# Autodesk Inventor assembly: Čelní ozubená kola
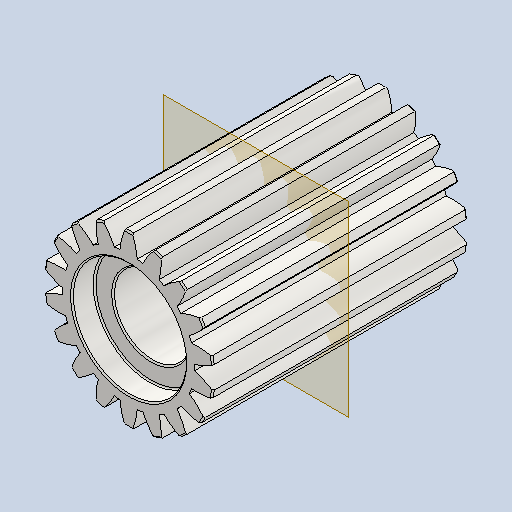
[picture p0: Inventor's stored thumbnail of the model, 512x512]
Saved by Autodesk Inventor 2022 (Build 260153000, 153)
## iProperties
ClientObjectVersion: 1
Created: 2025-05
Part Number: Čelní ozubená kola
Document SubType Name: Assembly
Designer: jbart
Categories: <?xml version="1.0" encoding="UTF-16"?> <MemberInstance><Categories><FamilyTemplate/><ParamToTemplateMap><ParamToTemplate><ParamToTemplate CategoryParameter="//
Mass: 8914.05 g
Surface Area: 1687.53 cm^2
Volume: 1135.55 cm^3
Density: 7.85 g/cm^3
Author: jbart
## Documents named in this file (2)
- C:\Users\jbart\OneDrive\Dokumenty\Inventor\Převodovka navijáku\Satelit B\Design Accelerator\Čelní ozubená kola1.iam
- C:\Users\jbart\OneDrive\Dokumenty\Inventor\Převodovka navijáku\Satelit B\Design Accelerator\Čelní ozubené kolo11.ipt
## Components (1 placed, 1 different names)
1. Čelní ozubené kolo1:1
